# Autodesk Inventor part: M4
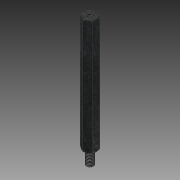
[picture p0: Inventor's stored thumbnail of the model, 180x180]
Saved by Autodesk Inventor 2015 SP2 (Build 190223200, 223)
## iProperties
Created: 2012-08
Part Number: M4
Material: Stahl
Document SubType Name: Modeling
Designer: rYan
Density: 7.85 g/cm^3
Mass: 1.74537 g
Surface Area: 3.04272 cm^2
Volume: 0.22234 cm^3
Appearance: Platte
Author: rYan
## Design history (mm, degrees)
derived "Abstandsbolzen Typ B.ipt"
feature "Volumenkörper1::Abstandsbolzen Typ B.ipt"
tag "Bezeichnung1"
node "Volumenkörper1"
other parameters: "SW" = 7, "L" = 65, "d2" = 0, "l_" = 9, "d9" = 118 deg, "GA_" = 4, "A_" = 8, "d13" = 0, "d17" = 0.25, "d20" = 45 deg
